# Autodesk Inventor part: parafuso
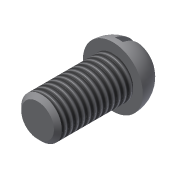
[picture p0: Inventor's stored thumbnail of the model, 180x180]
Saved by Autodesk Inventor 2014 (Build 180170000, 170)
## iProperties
Created: 2012-09
Part Number: parafuso
Material: Generic
Document SubType Name: Modeling
Designer: TR-06
Density: 1 g/cm^3
Appearance: Default(2)
Author: TR-06
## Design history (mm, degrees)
revolve "Revolution1" stored, may be unused: angle "d5" = 90 deg
sketch "Sketch2"
  geometry: L1 (3.479, 47.571)-(-2.571, 47.571); L2 (-2, 57.101)-(2, 57.101); L3 (2, 57.101)-(2, 41); L4 (2, 41)-(-2, 41); L5 (-2, 41)-(-2, 57.101); L6 (15.146, 38)-(-15.146, 38) reference; L7 (0, 57.101)-(0, 41); L8 (15.146, 38)-(-15.146, 38) reference; L9 (10.25, 38)-(-10.25, 38) reference; L10 (10.25, 0)-(-10.25, 0) reference; L11 (0, 38)-(0, 0); 1 further point
  constraints: 14 end point, 3 midpoint, 2 horizontal, 2 parallel, 2 perpendicular, 1 collinear
  dimensions: "d6" = 4 distance of L2.start L2.end; "d7" = 3 distance between parallel lines of L6 L4
extrude "Extrusion1" cut sketch "Sketch2" stored distance "d8" = 10; taper "d9" = 0 deg
chamfer "Chamfer1" distance "d10" = 2; stored, may be unused: second distance "d11" = 2, angle "d12" = 45 deg
feature "Rosca1" dims "d13" = 10, "d14" = 0
body "Solid1"
sketch "Sketch1"
  geometry: L1 (0, 0)-(-10.25, 0); L2 (-10.25, 0)-(-10.25, 38); L3 (-10.25, 38)-(-15.146, 38); L4 (0, 52.999)-(0, 0); A1 r 15 centre (-0.146, 38) between (0, 52.999) and (-15.146, 38)
  constraints: 8 end point, 2 perpendicular, 2 point on circle, 1 centre point, 1 horizontal, 1 parallel, 1 point on line
  dimensions: "d1" = 10.25 distance of L1.start L1.end; "d2" = 38 distance of L1.end L2.end; "d4" = 15 radius of A1
node "Projected Loop1"
node "Projected Loop2"
